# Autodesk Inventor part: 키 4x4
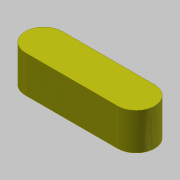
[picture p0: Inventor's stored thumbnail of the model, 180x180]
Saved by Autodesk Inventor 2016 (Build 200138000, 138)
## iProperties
Created: 2018-09
Part Number: 키 4x4
Document SubType Name: Modeling
Density: 7.86 g/cm^3
Material: 강철, 연강
Appearance: 노란색
Mass: 1.65269 g
Surface Area: 2.35398 cm^2
Volume: 0.210265 cm^3
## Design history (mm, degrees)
sketch "스케치1"
  geometry: L1 (-5, -2)-(5, -2); L2 (5, 2)-(-5, 2); A1 r 2 centre (5, 0) between (5, -2) and (5, 2); A2 r 2 centre (-5, 0) between (-5, 2) and (-5, -2); 2 further points
  constraints: 4 end point, 4 point on circle, 4 tangent, 2 centre point, 1 horizontal, 1 horizontal alignment, 1 midpoint, 1 parallel, 1 vertical alignment
  dimensions: "d0" = 4 distance between parallel lines of L1 L2; "d1" = 14 dimension on A1 A2
extrude "돌출1" new body sketch "스케치1" stored distance "d2" = 4; taper "d3" = 0 deg
node "솔리드1"
